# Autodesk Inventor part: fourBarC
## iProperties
Created: 2008-10
Part Number: fourBarC
Document SubType Name: Modeling
Designer: Lochan
Density: 1 g/cm^3
Mass: 2.09234 g
Surface Area: 21.6821 cm^2
Volume: 2.09234 cm^3
Author: Lochan
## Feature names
1. Extrusion1
2. Hole1
